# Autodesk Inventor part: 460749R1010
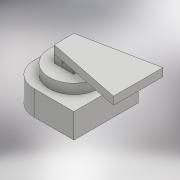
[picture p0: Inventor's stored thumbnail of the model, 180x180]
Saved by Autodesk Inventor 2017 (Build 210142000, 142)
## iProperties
Created: 2016-07
Part Number: 460749R1010
Material: Generic
Document SubType Name: Modeling
Designer: Polytech
Density: 1 g/cm^3
Appearance: Default
Author: Polytech
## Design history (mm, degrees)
sketch "Sketch1"
  geometry: C1 r 23 at (0, 0); 1 further point
  constraints: 1 centre point, 1 coincident
  dimensions: "d0" = 46 diameter of C1
extrude "Extrusion1" new body sketch "Sketch1" distance "d1" = 18; taper "d2" = 0 deg
sketch "Sketch2"
  geometry: L1 (-11.75, 48.75)-(48.75, 48.75); L2 (48.75, 48.75)-(48.75, -48.75); L3 (48.75, -48.75)-(-11.75, -48.75); L4 (-48.75, -11.75)-(-48.75, 11.75); L5 (-48.75, 48.75)-(48.75, -48.75); L6 (48.75, 48.75)-(-48.75, -48.75); A1 r 37 centre (-11.75, 11.75) between (-11.75, 48.75) and (-48.75, 11.75); A2 r 37 centre (-11.75, -11.75) between (-48.75, -11.75) and (-11.75, -48.75); 1 further point
  constraints: 12 end point, 4 point on circle, 4 point on line, 4 tangent, 2 centre point, 2 midpoint, 2 parallel, 1 equal radius, 1 horizontal, 1 perpendicular
  dimensions: "d3" = 97.5 distance of L2.end L6.end; "d4" = 97.5 distance of L1.end L2.end; "d5" = 37 radius of A1
extrude "Extrusion2" join sketch "Sketch2" distance "d6" = 37.5; taper "d7" = 0 deg
sketch "Sketch3"
  geometry: C1 r 37.5 at (0, 0); 1 further point
  constraints: 1 centre point, 1 coincident
  dimensions: "d8" = 75 diameter of C1
extrude "Extrusion3" join sketch "Sketch3" distance "d9" = 15; taper "d10" = 0 deg
sketch "Sketch4"
  geometry: L1 (-15, 15)-(15, 15); L2 (15, 15)-(15, -15); L3 (15, -15)-(-15, -15); L4 (-15, -15)-(-15, 15); L5 (-15, 15)-(15, -15); L6 (15, 15)-(-15, -15); 1 further point
  constraints: 12 end point, 2 midpoint, 2 parallel, 1 horizontal, 1 perpendicular
  dimensions: "d11" = 30 distance of L2.end L3.end; "d12" = 30 distance of L1.end L2.end
extrude "Extrusion4" join sketch "Sketch4" distance "d13" = 12; taper "d14" = 0 deg
sketch "Sketch5"
  geometry: L1 (-15, 6)-(15, 6); L2 (15, 6)-(15, -6); L3 (15, -6)-(-15, -6); L4 (-15, -6)-(-15, 6); L5 (-15, 6)-(15, -6); L6 (15, 6)-(-15, -6); 1 further point
  constraints: 12 end point, 2 midpoint, 2 parallel, 1 horizontal, 1 perpendicular
  dimensions: "d15" = 30 distance of L2.end L3.end; "d16" = 12 distance of L1.end L2.end
extrude "Extrusion5" cut sketch "Sketch5" distance "d17" = 12; taper "d18" = 0 deg
sketch "Sketch6"
  geometry: L1 (52.5, 0)-(-22.5, 0) reference; C1 r 3 at (15, 6); 1 further point
  constraints: 1 centre point, 1 vertical alignment
  dimensions: "d19" = 3 radius of C1; "d20" = 6 distance from line of L1 C1.centre
extrude "Extrusion6" cut sketch "Sketch6" stored distance "d21" = 0; taper "d22" = 0 deg
sketch "Sketch7"
  geometry: L1 (-15, 15)-(-15, -15); L2 (-15, -15)-(97.5, -37.5); L3 (97.5, -37.5)-(97.5, 37.5); L4 (97.5, 37.5)-(-15, 15); L5 (-15, -6)-(-15, -15) reference; 3 further points
  constraints: 8 end point, 2 horizontal alignment, 2 midpoint, 1 collinear, 1 parallel, 1 vertical
  dimensions: "d23" = 97.5 distance of point (97.5, 0) point (0, 0); "d24" = 75 distance of L2.end L3.end
extrude "Extrusion7" join sketch "Sketch7" distance "d25" = 12; taper "d26" = 0 deg
sketch "Sketch8"
  geometry: C1 r 23 at (0, 0); 1 further point
  constraints: 1 centre point, 1 coincident
  dimensions: "d27" = 46 diameter of C1
extrude "Extrusion8" cut sketch "Sketch8" distance "d28" = 24.5; taper "d29" = 0 deg
body "Solid1"
